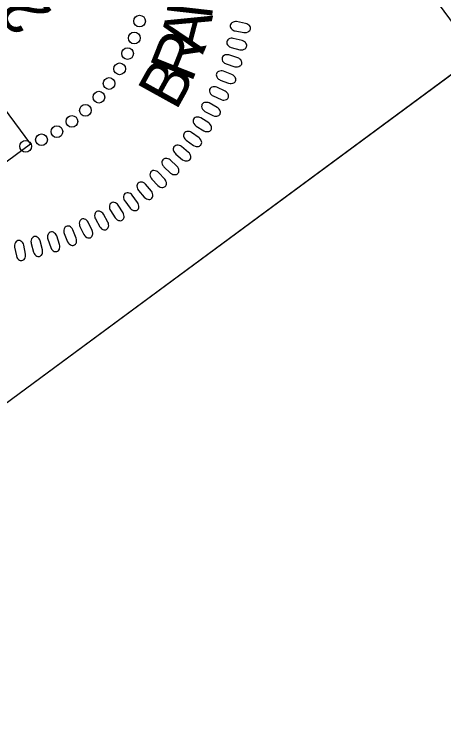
# Model space of a CAD drawing. Extents: x 474314 to 476195, y 501901 to 503905.
# Drawn here: x 474518.3 to 474577, y 503089.8 to 503188.4 of the extents above; entities that cross this region are included whole.
import ezdxf

# ---------------------------------------------------------------- set-up
doc = ezdxf.new("R2010")
doc.units = 0
for name, color, linetype in [('Sheet Clip Boundary CELL', 7, 'Continuous'), ('Sheet PE Seal Cell', 7, 'Continuous'), ('Sheet Plan CELL', 7, 'Continuous'), ('Sheet Sticker Incomplete CELL', 7, 'Continuous')]:
    doc.layers.add(name, color=color, linetype=linetype)

msp = doc.modelspace()

# ---------------------------------------------------------------- linework, layer by layer
at = {"layer": 'Sheet Clip Boundary CELL'}
msp.add_lwpolyline([(474600.428, 503196.681), (474460.82, 503093.562), (475070.851, 502267.556), (475070.851, 502267.556), (475070.851, 502267.556), (475070.851, 502267.556), (475070.851, 502267.556), (475070.851, 502267.556), (475422.164, 502337.988), (475422.164, 502337.988), (476046.454, 502713.989), (475412.072, 503572.987), (475380.25, 503549.486), (475256.124, 503717.563), (475223.58, 503693.529), (475026.19, 503617.593), (474539.959, 503278.507)], close=True, dxfattribs=at)
at = {"layer": 'Sheet PE Seal Cell'}
for points in [[(474548.503, 503186.121), (474549.71, 503185.9), (474549.932, 503185.897), (474550.079, 503185.923), (474550.266, 503186.003), (474550.392, 503186.079), (474550.49, 503186.175), (474550.549, 503186.271), (474550.588, 503186.378), (474550.589, 503186.492), (474550.581, 503186.615), (474550.541, 503186.728), (474550.461, 503186.849), (474550.394, 503186.922), (474550.259, 503187.016), (474550.093, 503187.107), (474549.94, 503187.158), (474548.706, 503187.391), (474548.535, 503187.4), (474548.389, 503187.38), (474548.216, 503187.321), (474548.059, 503187.236), (474547.963, 503187.155), (474547.875, 503187.011), (474547.829, 503186.867), (474547.841, 503186.713), (474547.872, 503186.601), (474547.947, 503186.458), (474548.092, 503186.31), (474548.257, 503186.211), (474548.379, 503186.159)], [(474547.976, 503183.854), (474549.167, 503183.558), (474549.388, 503183.541), (474549.537, 503183.558), (474549.728, 503183.626), (474549.858, 503183.694), (474549.963, 503183.783), (474550.027, 503183.875), (474550.073, 503183.98), (474550.081, 503184.093), (474550.08, 503184.216), (474550.048, 503184.332), (474549.976, 503184.458), (474549.913, 503184.535), (474549.784, 503184.637), (474549.624, 503184.738), (474549.476, 503184.798), (474548.257, 503185.109), (474548.088, 503185.128), (474547.941, 503185.118), (474547.765, 503185.07), (474547.602, 503184.995), (474547.501, 503184.92), (474547.405, 503184.782), (474547.35, 503184.641), (474547.353, 503184.487), (474547.376, 503184.373), (474547.442, 503184.226), (474547.577, 503184.069), (474547.736, 503183.96), (474547.854, 503183.9)], [(474547.296, 503181.608), (474548.466, 503181.237), (474548.686, 503181.207), (474548.836, 503181.213), (474549.031, 503181.27), (474549.165, 503181.33), (474549.275, 503181.413), (474549.344, 503181.5), (474549.398, 503181.601), (474549.412, 503181.714), (474549.42, 503181.837), (474549.394, 503181.955), (474549.331, 503182.085), (474549.273, 503182.166), (474549.15, 503182.275), (474548.998, 503182.386), (474548.852, 503182.456), (474547.657, 503182.842), (474547.488, 503182.872), (474547.341, 503182.871), (474547.162, 503182.834), (474546.996, 503182.77), (474546.89, 503182.701), (474546.785, 503182.569), (474546.721, 503182.432), (474546.714, 503182.278), (474546.73, 503182.163), (474546.786, 503182.012), (474546.912, 503181.847), (474547.063, 503181.728), (474547.177, 503181.661)], [(474546.466, 503179.408), (474547.611, 503178.964), (474547.828, 503178.92), (474547.977, 503178.918), (474548.176, 503178.962), (474548.313, 503179.012), (474548.428, 503179.088), (474548.503, 503179.172), (474548.562, 503179.269), (474548.584, 503179.381), (474548.599, 503179.503), (474548.582, 503179.622), (474548.526, 503179.756), (474548.474, 503179.84), (474548.358, 503179.957), (474548.212, 503180.078), (474548.072, 503180.156), (474546.903, 503180.617), (474546.737, 503180.658), (474546.59, 503180.666), (474546.409, 503180.64), (474546.238, 503180.586), (474546.129, 503180.524), (474546.016, 503180.399), (474545.944, 503180.267), (474545.927, 503180.113), (474545.936, 503179.998), (474545.983, 503179.843), (474546.098, 503179.67), (474546.241, 503179.542), (474546.351, 503179.468)], [(474545.484, 503177.245), (474546.598, 503176.731), (474546.813, 503176.673), (474546.962, 503176.662), (474547.162, 503176.692), (474547.303, 503176.735), (474547.422, 503176.803), (474547.502, 503176.881), (474547.568, 503176.975), (474547.596, 503177.085), (474547.619, 503177.207), (474547.609, 503177.326), (474547.562, 503177.463), (474547.515, 503177.551), (474547.407, 503177.675), (474547.269, 503177.804), (474547.134, 503177.892), (474545.996, 503178.425), (474545.832, 503178.475), (474545.687, 503178.493), (474545.504, 503178.478), (474545.331, 503178.435), (474545.217, 503178.38), (474545.098, 503178.263), (474545.017, 503178.135), (474544.99, 503177.983), (474544.992, 503177.867), (474545.029, 503177.71), (474545.133, 503177.531), (474545.268, 503177.394), (474545.373, 503177.313)], [(474544.378, 503175.126), (474545.457, 503174.543), (474545.668, 503174.472), (474545.816, 503174.451), (474546.018, 503174.47), (474546.161, 503174.503), (474546.285, 503174.564), (474546.369, 503174.637), (474546.44, 503174.726), (474546.476, 503174.834), (474546.506, 503174.954), (474546.504, 503175.074), (474546.465, 503175.213), (474546.424, 503175.304), (474546.324, 503175.434), (474546.194, 503175.572), (474546.065, 503175.668), (474544.963, 503176.272), (474544.802, 503176.332), (474544.659, 503176.359), (474544.476, 503176.356), (474544.299, 503176.324), (474544.183, 503176.276), (474544.056, 503176.166), (474543.967, 503176.044), (474543.931, 503175.894), (474543.926, 503175.778), (474543.952, 503175.619), (474544.045, 503175.434), (474544.171, 503175.288), (474544.271, 503175.201)], [(474543.175, 503173.12), (474544.216, 503172.47), (474544.422, 503172.385), (474544.568, 503172.355), (474544.771, 503172.361), (474544.916, 503172.385), (474545.043, 503172.439), (474545.132, 503172.506), (474545.209, 503172.59), (474545.251, 503172.696), (474545.289, 503172.813), (474545.294, 503172.933), (474545.264, 503173.075), (474545.228, 503173.168), (474545.137, 503173.305), (474545.016, 503173.45), (474544.893, 503173.554), (474543.831, 503174.226), (474543.675, 503174.297), (474543.533, 503174.332), (474543.35, 503174.341), (474543.172, 503174.319), (474543.053, 503174.279), (474542.919, 503174.178), (474542.823, 503174.061), (474542.778, 503173.914), (474542.765, 503173.798), (474542.782, 503173.638), (474542.863, 503173.447), (474542.979, 503173.294), (474543.074, 503173.201)], [(474541.826, 503171.18), (474542.824, 503170.467), (474543.024, 503170.369), (474543.168, 503170.33), (474543.372, 503170.323), (474543.518, 503170.338), (474543.648, 503170.383), (474543.741, 503170.445), (474543.822, 503170.524), (474543.871, 503170.627), (474543.916, 503170.742), (474543.929, 503170.862), (474543.908, 503171.005), (474543.879, 503171.1), (474543.796, 503171.242), (474543.684, 503171.395), (474543.568, 503171.506), (474542.55, 503172.243), (474542.399, 503172.323), (474542.259, 503172.368), (474542.078, 503172.388), (474541.899, 503172.378), (474541.777, 503172.346), (474541.637, 503172.252), (474541.534, 503172.142), (474541.48, 503171.998), (474541.459, 503171.884), (474541.466, 503171.723), (474541.535, 503171.527), (474541.641, 503171.367), (474541.73, 503171.268)], [(474540.378, 503169.297), (474541.329, 503168.522), (474541.522, 503168.413), (474541.664, 503168.365), (474541.866, 503168.345), (474542.013, 503168.351), (474542.145, 503168.388), (474542.242, 503168.444), (474542.328, 503168.518), (474542.383, 503168.617), (474542.436, 503168.729), (474542.456, 503168.847), (474542.444, 503168.992), (474542.421, 503169.089), (474542.347, 503169.235), (474542.245, 503169.395), (474542.136, 503169.513), (474541.167, 503170.313), (474541.021, 503170.403), (474540.884, 503170.456), (474540.704, 503170.487), (474540.525, 503170.489), (474540.402, 503170.464), (474540.256, 503170.38), (474540.146, 503170.276), (474540.083, 503170.135), (474540.056, 503170.022), (474540.052, 503169.861), (474540.109, 503169.662), (474540.205, 503169.495), (474540.287, 503169.391)], [(474538.779, 503167.521), (474539.68, 503166.688), (474539.866, 503166.566), (474540.004, 503166.509), (474540.205, 503166.477), (474540.352, 503166.473), (474540.486, 503166.502), (474540.586, 503166.551), (474540.677, 503166.62), (474540.738, 503166.716), (474540.797, 503166.824), (474540.825, 503166.941), (474540.823, 503167.086), (474540.805, 503167.184), (474540.741, 503167.336), (474540.65, 503167.501), (474540.548, 503167.626), (474539.63, 503168.485), (474539.491, 503168.583), (474539.358, 503168.645), (474539.18, 503168.687), (474539.001, 503168.7), (474538.877, 503168.683), (474538.726, 503168.609), (474538.61, 503168.512), (474538.538, 503168.376), (474538.503, 503168.265), (474538.49, 503168.104), (474538.533, 503167.901), (474538.62, 503167.729), (474538.695, 503167.62)], [(474537.107, 503165.871), (474537.953, 503164.983), (474538.132, 503164.851), (474538.266, 503164.785), (474538.464, 503164.74), (474538.61, 503164.727), (474538.746, 503164.747), (474538.849, 503164.79), (474538.945, 503164.854), (474539.012, 503164.945), (474539.078, 503165.049), (474539.113, 503165.165), (474539.119, 503165.309), (474539.107, 503165.409), (474539.053, 503165.563), (474538.972, 503165.734), (474538.879, 503165.865), (474538.017, 503166.78), (474537.884, 503166.887), (474537.755, 503166.957), (474537.58, 503167.011), (474537.403, 503167.035), (474537.277, 503167.026), (474537.122, 503166.96), (474537, 503166.871), (474536.919, 503166.739), (474536.878, 503166.631), (474536.854, 503166.471), (474536.885, 503166.266), (474536.961, 503166.09), (474537.029, 503165.975)], [(474535.289, 503164.324), (474536.078, 503163.384), (474536.248, 503163.241), (474536.377, 503163.167), (474536.573, 503163.11), (474536.718, 503163.088), (474536.855, 503163.099), (474536.961, 503163.136), (474537.06, 503163.193), (474537.132, 503163.28), (474537.204, 503163.381), (474537.247, 503163.493), (474537.262, 503163.637), (474537.257, 503163.736), (474537.212, 503163.894), (474537.142, 503164.07), (474537.057, 503164.206), (474536.254, 503165.174), (474536.128, 503165.289), (474536.004, 503165.367), (474535.833, 503165.431), (474535.657, 503165.466), (474535.532, 503165.465), (474535.373, 503165.41), (474535.245, 503165.329), (474535.157, 503165.202), (474535.108, 503165.097), (474535.075, 503164.939), (474535.093, 503164.732), (474535.157, 503164.551), (474535.217, 503164.433)], [(474533.424, 503162.881), (474534.152, 503161.894), (474534.313, 503161.74), (474534.438, 503161.658), (474534.629, 503161.589), (474534.772, 503161.558), (474534.91, 503161.561), (474535.017, 503161.591), (474535.12, 503161.641), (474535.197, 503161.724), (474535.276, 503161.819), (474535.325, 503161.929), (474535.35, 503162.072), (474535.351, 503162.171), (474535.316, 503162.332), (474535.257, 503162.512), (474535.181, 503162.653), (474534.44, 503163.669), (474534.322, 503163.792), (474534.203, 503163.878), (474534.036, 503163.952), (474533.863, 503163.999), (474533.737, 503164.005), (474533.575, 503163.96), (474533.443, 503163.887), (474533.347, 503163.766), (474533.293, 503163.664), (474533.249, 503163.508), (474533.253, 503163.301), (474533.306, 503163.117), (474533.359, 503162.994)], [(474531.456, 503161.59), (474532.12, 503160.559), (474532.271, 503160.394), (474532.391, 503160.305), (474532.577, 503160.223), (474532.718, 503160.184), (474532.855, 503160.178), (474532.965, 503160.201), (474533.07, 503160.245), (474533.153, 503160.323), (474533.238, 503160.413), (474533.293, 503160.519), (474533.327, 503160.66), (474533.334, 503160.76), (474533.31, 503160.922), (474533.263, 503161.105), (474533.195, 503161.251), (474532.52, 503162.312), (474532.409, 503162.442), (474532.296, 503162.534), (474532.133, 503162.62), (474531.964, 503162.677), (474531.839, 503162.691), (474531.675, 503162.656), (474531.538, 503162.592), (474531.434, 503162.477), (474531.373, 503162.378), (474531.32, 503162.226), (474531.312, 503162.019), (474531.352, 503161.831), (474531.398, 503161.706)], [(474529.4, 503160.427), (474529.999, 503159.357), (474530.138, 503159.184), (474530.252, 503159.087), (474530.433, 503158.994), (474530.571, 503158.945), (474530.708, 503158.931), (474530.819, 503158.947), (474530.927, 503158.984), (474531.014, 503159.057), (474531.105, 503159.141), (474531.167, 503159.244), (474531.209, 503159.383), (474531.222, 503159.482), (474531.208, 503159.645), (474531.173, 503159.83), (474531.114, 503159.981), (474530.507, 503161.081), (474530.405, 503161.218), (474530.298, 503161.318), (474530.142, 503161.413), (474529.975, 503161.48), (474529.851, 503161.502), (474529.685, 503161.478), (474529.545, 503161.423), (474529.434, 503161.315), (474529.367, 503161.22), (474529.305, 503161.071), (474529.284, 503160.865), (474529.312, 503160.675), (474529.35, 503160.548)], [(474527.288, 503159.391), (474527.819, 503158.285), (474527.948, 503158.103), (474528.055, 503157.999), (474528.23, 503157.895), (474528.365, 503157.838), (474528.501, 503157.815), (474528.612, 503157.824), (474528.722, 503157.854), (474528.814, 503157.921), (474528.909, 503158), (474528.977, 503158.099), (474529.028, 503158.234), (474529.048, 503158.332), (474529.044, 503158.496), (474529.02, 503158.684), (474528.972, 503158.837), (474528.435, 503159.974), (474528.341, 503160.117), (474528.24, 503160.223), (474528.09, 503160.328), (474527.929, 503160.406), (474527.807, 503160.435), (474527.639, 503160.422), (474527.496, 503160.375), (474527.378, 503160.274), (474527.306, 503160.184), (474527.234, 503160.039), (474527.199, 503159.835), (474527.217, 503159.643), (474527.246, 503159.514)], [(474525.138, 503158.438), (474525.598, 503157.301), (474525.715, 503157.112), (474525.816, 503157.001), (474525.984, 503156.886), (474526.115, 503156.821), (474526.249, 503156.789), (474526.361, 503156.792), (474526.472, 503156.815), (474526.568, 503156.875), (474526.668, 503156.948), (474526.743, 503157.043), (474526.802, 503157.174), (474526.828, 503157.271), (474526.834, 503157.435), (474526.822, 503157.624), (474526.783, 503157.78), (474526.319, 503158.948), (474526.234, 503159.097), (474526.14, 503159.209), (474525.997, 503159.323), (474525.842, 503159.411), (474525.721, 503159.448), (474525.553, 503159.445), (474525.407, 503159.407), (474525.284, 503159.314), (474525.205, 503159.229), (474525.125, 503159.089), (474525.078, 503158.887), (474525.082, 503158.695), (474525.104, 503158.564)], [(474520.624, 503157.069), (474520.938, 503155.883), (474521.03, 503155.681), (474521.116, 503155.559), (474521.268, 503155.423), (474521.39, 503155.342), (474521.519, 503155.294), (474521.631, 503155.283), (474521.744, 503155.292), (474521.847, 503155.34), (474521.955, 503155.4), (474522.041, 503155.483), (474522.116, 503155.607), (474522.154, 503155.699), (474522.181, 503155.861), (474522.192, 503156.05), (474522.173, 503156.21), (474521.859, 503157.426), (474521.794, 503157.584), (474521.715, 503157.708), (474521.588, 503157.839), (474521.443, 503157.946), (474521.329, 503157.998), (474521.162, 503158.016), (474521.013, 503157.997), (474520.878, 503157.92), (474520.79, 503157.845), (474520.692, 503157.716), (474520.62, 503157.522), (474520.601, 503157.331), (474520.606, 503157.197)], [(474522.905, 503157.665), (474523.293, 503156.501), (474523.398, 503156.305), (474523.491, 503156.188), (474523.651, 503156.063), (474523.779, 503155.99), (474523.91, 503155.95), (474524.021, 503155.945), (474524.135, 503155.962), (474524.234, 503156.016), (474524.339, 503156.082), (474524.419, 503156.172), (474524.487, 503156.299), (474524.518, 503156.394), (474524.535, 503156.558), (474524.535, 503156.746), (474524.506, 503156.905), (474524.116, 503158.1), (474524.041, 503158.253), (474523.954, 503158.372), (474523.818, 503158.495), (474523.668, 503158.591), (474523.55, 503158.637), (474523.383, 503158.644), (474523.235, 503158.616), (474523.105, 503158.53), (474523.022, 503158.45), (474522.932, 503158.315), (474522.873, 503158.117), (474522.866, 503157.925), (474522.878, 503157.792)], [(474518.361, 503156.566), (474518.6, 503155.362), (474518.679, 503155.154), (474518.758, 503155.027), (474518.901, 503154.883), (474519.018, 503154.794), (474519.143, 503154.738), (474519.254, 503154.719), (474519.368, 503154.722), (474519.474, 503154.763), (474519.585, 503154.816), (474519.676, 503154.894), (474519.759, 503155.013), (474519.802, 503155.103), (474519.839, 503155.263), (474519.863, 503155.451), (474519.855, 503155.611), (474519.617, 503156.846), (474519.561, 503157.007), (474519.49, 503157.135), (474519.371, 503157.274), (474519.234, 503157.389), (474519.124, 503157.449), (474518.958, 503157.477), (474518.807, 503157.467), (474518.669, 503157.399), (474518.575, 503157.33), (474518.47, 503157.207), (474518.386, 503157.018), (474518.355, 503156.829), (474518.351, 503156.695)]]:
    msp.add_lwpolyline(points, close=True, dxfattribs=at)
for centre in [(474535.436, 503187.469), (474534.717, 503185.157), (474533.799, 503183.026), (474532.715, 503180.939), (474531.273, 503178.935), (474529.88, 503177.066), (474528.041, 503175.263), (474526.189, 503173.748), (474524.141, 503172.355), (474522.037, 503171.248), (474519.879, 503170.348)]:
    msp.add_circle(centre, 0.801, dxfattribs=at)
at = {"layer": 'Sheet Plan CELL'}
msp.add_lwpolyline([(474491.045, 503115.885), (474431.609, 503196.366), (474522.115, 503263.206), (474581.524, 503182.72)], close=True, dxfattribs=at)
at = {"layer": 'Sheet Sticker Incomplete CELL'}
msp.add_lwpolyline([(474520.521, 503170.658), (474501.617, 503156.697), (474414.289, 503274.946), (474433.193, 503288.907)], close=True, dxfattribs=at)

# ---------------------------------------------------------------- texts
at = {"layer": 'Sheet PE Seal Cell'}
for s, height, rotation, p in [('29470', 6.2363, 126.42771, (474523.652, 503188.65)), ('N', 6.236, 83.53909, (474545.295, 503187.557)), ('A', 6.236, 75.42791, (474544.11, 503182.854)), ('R', 6.236, 68.31107, (474542.531, 503178.9)), ('B', 6.236, 61.03604, (474540.425, 503175.093))]:
    msp.add_text(s, height=height, rotation=rotation, dxfattribs=at).set_placement(p)

doc.saveas('drawing.dxf')
